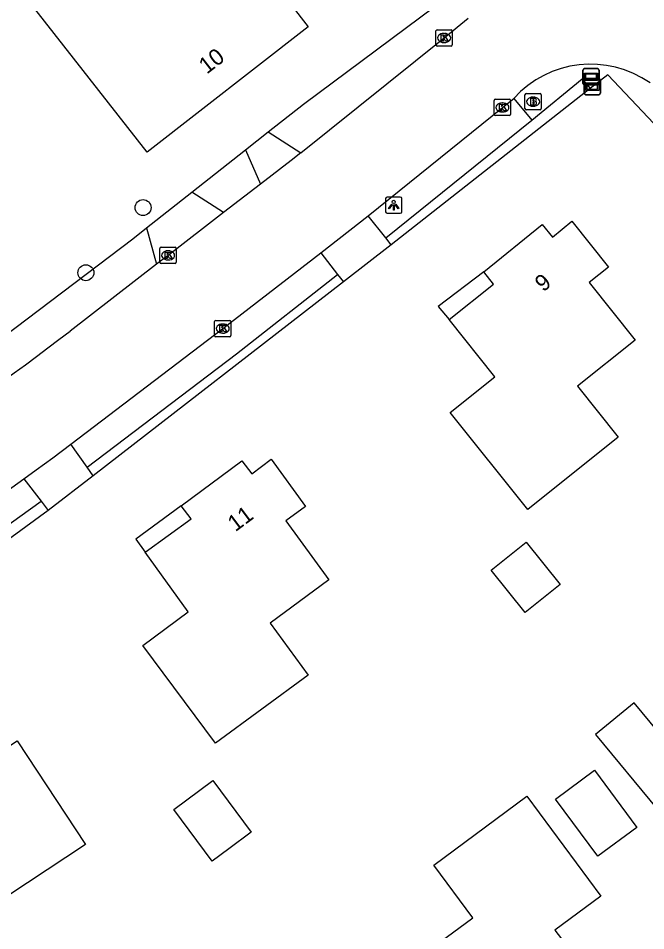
# Model space of a CAD drawing. Extents: x 162675 to 163482, y 379761 to 381227.
# Drawn here: x 163292.2 to 163330.7, y 380792.3 to 380848.3 of the extents above; entities that cross this region are included whole.
import ezdxf

# ---------------------------------------------------------------- set-up
doc = ezdxf.new("R2010")
doc.units = 0
for name, color, linetype in [('IMGEO_Boom', 7, 'Continuous'), ('IMGEO_Brandkraan', 7, 'Continuous'), ('IMGEO_Groenvoorziening', 7, 'Continuous'), ('IMGEO_Haag', 7, 'Continuous'), ('IMGEO_Kolk', 7, 'Continuous'), ('IMGEO_Lichtpunt', 7, 'Continuous'), ('IMGEO_Pand', 7, 'Continuous'), ('IMGEO_Pand_nummerreeks', 7, 'Continuous'), ('IMGEO_Pand_overbouw', 7, 'Continuous'), ('IMGEO_Parkeervlak_halfverhard', 7, 'Continuous'), ('IMGEO_Rijbaan_lokaal_gesloten', 7, 'Continuous'), ('IMGEO_Straatnaambord', 7, 'Continuous'), ('IMGEO_Verklikker', 7, 'Continuous'), ('IMGEO_Voetpad_halfverhard', 7, 'Continuous'), ('IMGEO_Voetpad_open', 7, 'Continuous')]:
    doc.layers.add(name, color=color, linetype=linetype)

msp = doc.modelspace()

# ---------------------------------------------------------------- linework, layer by layer
at = {"layer": 'IMGEO_Boom'}
for centre in [(163299.893, 380836.661), (163296.387, 380832.674)]:
    msp.add_circle(centre, 0.489, dxfattribs=at)
at = {"layer": 'IMGEO_Brandkraan'}
for p, q in [((163323.383, 380843.654), (163324.235, 380843.654)), ((163323.308, 380842.728), (163323.308, 380843.58)), ((163323.796, 380843.434), (163323.821, 380843.434)), ((163324.309, 380843.58), (163324.309, 380842.728)), ((163324.235, 380842.654), (163323.383, 380842.654)), ((163323.819, 380842.874), (163323.794, 380842.874))]:
    msp.add_line(p, q, dxfattribs=at)
for points in [[(163323.383, 380843.654), (163324.235, 380843.654)], [(163323.308, 380842.728), (163323.308, 380843.58)], [(163323.656, 380843.354), (163323.656, 380842.954), (163323.869, 380842.954)], [(163323.887, 380843.354), (163323.656, 380843.354)], [(163323.835, 380843.273), (163323.781, 380843.273), (163323.781, 380843.197)], [(163323.781, 380843.197), (163323.834, 380843.197)], [(163323.843, 380843.121), (163323.781, 380843.121), (163323.781, 380843.04)], [(163324.309, 380843.58), (163324.309, 380842.728)], [(163324.235, 380842.654), (163323.383, 380842.654)], [(163323.781, 380843.04), (163323.843, 380843.04)]]:
    msp.add_lwpolyline(points, dxfattribs=at)
for centre, radius, start, end in [((163323.385, 380843.578), 0.0765, 91.552, 178.448), ((163323.385, 380843.578), 0.0765, 91.552, 178.448), ((163324.233, 380843.578), 0.0765, 1.552, 88.448), ((163324.233, 380843.578), 0.0765, 1.552, 88.448), ((163323.836, 380843.235), 0.0379, 267.8285, 90.9355), ((163323.844, 380843.08), 0.0404, 269.8759, 90.5077), ((163323.891, 380843.209), 0.145, 59.4692, 91.5367), ((163323.916, 380843.256), 0.0922, 285.5137, 58.1501), ((163323.921, 380843.064), 0.105, 301.3115, 78.989), ((163323.385, 380842.73), 0.0765, 181.552, 268.448), ((163323.385, 380842.73), 0.0765, 181.552, 268.448), ((163323.875, 380843.205), 0.251, 268.6676, 293.5347), ((163324.233, 380842.73), 0.0765, 271.552, 358.448), ((163324.233, 380842.73), 0.0765, 271.552, 358.448)]:
    msp.add_arc(centre, radius, start, end, dxfattribs=at)
for centre, major_axis, ratio, start_param, end_param in [((163323.795, 380843.154), (-0.387, 0.002), 0.722429, 4.712389, 7.853982), ((163323.82, 380843.154), (-0.39, 0.002), 0.717154, 1.570796, 4.712389)]:
    msp.add_ellipse(centre, major_axis=major_axis, ratio=ratio, start_param=start_param, end_param=end_param, dxfattribs=at)
at = {"layer": 'IMGEO_Groenvoorziening'}
for points in [[(163307.569, 380841.308), (163309.722, 380843.007), (163318.685, 380849.672)], [(163358.343, 380813.122), (163328.383, 380844.802), (163327.309, 380843.958)], [(163302.894, 380837.618), (163306.169, 380840.203)], [(163271.872, 380815.173), (163286.296, 380824.946), (163299.265, 380834.754), (163300.104, 380835.416)]]:
    msp.add_lwpolyline(points, dxfattribs=at)
at = {"layer": 'IMGEO_Haag'}
for points in [[(163323.72, 380842.014), (163326.824, 380844.551), (163327.309, 380843.958)], [(163327.309, 380843.958), (163315.112, 380834.375)], [(163312.188, 380832.112), (163296.843, 380820.233)], [(163294.076, 380818.108), (163289.632, 380814.871), (163286.499, 380812.86)]]:
    msp.add_lwpolyline(points, dxfattribs=at)
at = {"layer": 'IMGEO_Kolk'}
for p, q in [((163317.928, 380847.559), (163318.78, 380847.559)), ((163317.853, 380846.633), (163317.853, 380847.485)), ((163318.341, 380847.339), (163318.366, 380847.339)), ((163318.854, 380847.485), (163318.854, 380846.633)), ((163318.78, 380846.559), (163317.928, 380846.559)), ((163318.364, 380846.779), (163318.339, 380846.779)), ((163321.425, 380842.375), (163321.425, 380843.227)), ((163321.5, 380843.301), (163322.352, 380843.301)), ((163321.913, 380843.081), (163321.938, 380843.081)), ((163322.426, 380843.227), (163322.426, 380842.375)), ((163321.936, 380842.521), (163321.911, 380842.521)), ((163322.352, 380842.301), (163321.5, 380842.301)), ((163300.928, 380833.309), (163300.928, 380834.161)), ((163301.003, 380834.235), (163301.855, 380834.235)), ((163301.929, 380834.161), (163301.929, 380833.309)), ((163301.416, 380834.015), (163301.441, 380834.015)), ((163301.855, 380833.235), (163301.003, 380833.235)), ((163301.439, 380833.455), (163301.414, 380833.455)), ((163304.281, 380828.822), (163304.281, 380829.674)), ((163304.356, 380829.748), (163305.208, 380829.748)), ((163305.282, 380829.674), (163305.282, 380828.822)), ((163304.769, 380829.528), (163304.794, 380829.528)), ((163305.208, 380828.748), (163304.356, 380828.748)), ((163304.792, 380828.968), (163304.767, 380828.968))]:
    msp.add_line(p, q, dxfattribs=at)
for points in [[(163317.928, 380847.559), (163318.78, 380847.559)], [(163317.853, 380846.633), (163317.853, 380847.485)], [(163318.174, 380847.259), (163318.297, 380847.259), (163318.297, 380847.108), (163318.427, 380847.259), (163318.591, 380847.259), (163318.445, 380847.108), (163318.598, 380846.859), (163318.446, 380846.859), (163318.361, 380847.023), (163318.297, 380846.956), (163318.297, 380846.859), (163318.174, 380846.859), (163318.174, 380847.259)], [(163318.854, 380847.485), (163318.854, 380846.633)], [(163318.78, 380846.559), (163317.928, 380846.559)], [(163321.425, 380842.375), (163321.425, 380843.227)], [(163321.5, 380843.301), (163322.352, 380843.301)], [(163322.426, 380843.227), (163322.426, 380842.375)], [(163321.746, 380843.001), (163321.869, 380843.001), (163321.869, 380842.85), (163321.999, 380843.001), (163322.163, 380843.001), (163322.017, 380842.85), (163322.17, 380842.601), (163322.018, 380842.601), (163321.933, 380842.765), (163321.869, 380842.698), (163321.869, 380842.601), (163321.746, 380842.601), (163321.746, 380843.001)], [(163322.352, 380842.301), (163321.5, 380842.301)], [(163300.928, 380833.309), (163300.928, 380834.161)], [(163301.003, 380834.235), (163301.855, 380834.235)], [(163301.929, 380834.161), (163301.929, 380833.309)], [(163301.249, 380833.935), (163301.372, 380833.935), (163301.372, 380833.784), (163301.502, 380833.935), (163301.666, 380833.935), (163301.52, 380833.784), (163301.673, 380833.535), (163301.521, 380833.535), (163301.436, 380833.699), (163301.372, 380833.632), (163301.372, 380833.535), (163301.249, 380833.535), (163301.249, 380833.935)], [(163301.855, 380833.235), (163301.003, 380833.235)], [(163304.281, 380828.822), (163304.281, 380829.674)], [(163304.356, 380829.748), (163305.208, 380829.748)], [(163305.282, 380829.674), (163305.282, 380828.822)], [(163304.602, 380829.448), (163304.725, 380829.448), (163304.725, 380829.297), (163304.855, 380829.448), (163305.019, 380829.448), (163304.873, 380829.297), (163305.026, 380829.048), (163304.874, 380829.048), (163304.789, 380829.212), (163304.725, 380829.145), (163304.725, 380829.048), (163304.602, 380829.048), (163304.602, 380829.448)], [(163305.208, 380828.748), (163304.356, 380828.748)]]:
    msp.add_lwpolyline(points, dxfattribs=at)
for centre, start, end in [((163317.93, 380847.483), 91.552, 178.448), ((163317.93, 380847.483), 91.552, 178.448), ((163318.778, 380847.483), 1.552, 88.448), ((163318.778, 380847.483), 1.552, 88.448), ((163317.93, 380846.635), 181.552, 268.448), ((163317.93, 380846.635), 181.552, 268.448), ((163318.778, 380846.635), 271.552, 358.448), ((163318.778, 380846.635), 271.552, 358.448), ((163321.502, 380843.225), 91.552, 178.448), ((163321.502, 380843.225), 91.552, 178.448), ((163322.35, 380843.225), 1.552, 88.448), ((163322.35, 380843.225), 1.552, 88.448), ((163321.502, 380842.377), 181.552, 268.448), ((163321.502, 380842.377), 181.552, 268.448), ((163322.35, 380842.377), 271.552, 358.448), ((163322.35, 380842.377), 271.552, 358.448), ((163301.005, 380834.159), 91.552, 178.448), ((163301.005, 380834.159), 91.552, 178.448), ((163301.853, 380834.159), 1.552, 88.448), ((163301.853, 380834.159), 1.552, 88.448), ((163301.005, 380833.311), 181.552, 268.448), ((163301.005, 380833.311), 181.552, 268.448), ((163301.853, 380833.311), 271.552, 358.448), ((163301.853, 380833.311), 271.552, 358.448), ((163304.358, 380829.672), 91.552, 178.448), ((163304.358, 380829.672), 91.552, 178.448), ((163305.206, 380829.672), 1.552, 88.448), ((163305.206, 380829.672), 1.552, 88.448), ((163304.358, 380828.824), 181.552, 268.448), ((163304.358, 380828.824), 181.552, 268.448), ((163305.206, 380828.824), 271.552, 358.448), ((163305.206, 380828.824), 271.552, 358.448)]:
    msp.add_arc(centre, 0.0765, start, end, dxfattribs=at)
for centre, major_axis, ratio, start_param, end_param in [((163318.34, 380847.059), (-0.387, 0.002), 0.722429, 4.712389, 7.853982), ((163318.365, 380847.059), (-0.39, 0.002), 0.717154, 1.570796, 4.712389), ((163321.912, 380842.801), (-0.387, 0.002), 0.722429, 4.712389, 7.853982), ((163321.937, 380842.801), (-0.39, 0.002), 0.717154, 1.570796, 4.712389), ((163301.415, 380833.735), (-0.387, 0.002), 0.722429, 4.712389, 7.853982), ((163301.44, 380833.735), (-0.39, 0.002), 0.717154, 1.570796, 4.712389), ((163304.768, 380829.248), (-0.387, 0.002), 0.722429, 4.712389, 7.853982), ((163304.793, 380829.248), (-0.39, 0.002), 0.717154, 1.570796, 4.712389)]:
    msp.add_ellipse(centre, major_axis=major_axis, ratio=ratio, start_param=start_param, end_param=end_param, dxfattribs=at)
at = {"layer": 'IMGEO_Lichtpunt'}
for p, q in [((163314.762, 380837.214), (163314.762, 380836.407)), ((163314.762, 380837.214), (163314.762, 380836.407)), ((163315.664, 380837.309), (163314.856, 380837.309)), ((163315.664, 380837.309), (163314.856, 380837.309)), ((163315.758, 380836.407), (163315.758, 380837.214)), ((163315.758, 380836.407), (163315.758, 380837.214)), ((163314.856, 380836.313), (163315.664, 380836.313)), ((163314.856, 380836.313), (163315.664, 380836.313))]:
    msp.add_line(p, q, dxfattribs=at)
for points in [[(163315.136, 380836.878), (163315.175, 380836.85), (163314.987, 380836.588), (163314.949, 380836.615), (163315.136, 380836.878)], [(163315.238, 380836.83), (163315.285, 380836.83), (163315.285, 380836.508), (163315.238, 380836.508), (163315.238, 380836.83)], [(163315.348, 380836.85), (163315.386, 380836.877), (163315.573, 380836.615), (163315.534, 380836.587), (163315.348, 380836.85)]]:
    msp.add_lwpolyline(points, dxfattribs=at)
msp.add_circle((163315.261, 380837.012), 0.0994, dxfattribs=at)
for centre, start, end in [((163314.856, 380837.214), 90, 180), ((163314.856, 380837.214), 90, 180), ((163315.664, 380837.214), 0, 90), ((163315.664, 380837.214), 0, 90), ((163314.856, 380836.407), 180, 270), ((163314.856, 380836.407), 180, 270), ((163315.664, 380836.407), 270, 0), ((163315.664, 380836.407), 270, 360)]:
    msp.add_arc(centre, 0.0946, start, end, dxfattribs=at)
at = {"layer": 'IMGEO_Pand'}
for points in [[(163296.403, 380852.525), (163298.244, 380850.163), (163304.416, 380854.973), (163310.02, 380847.748), (163300.136, 380840.05), (163292.666, 380849.618), (163296.403, 380852.525)], [(163320.778, 380832.718), (163324.371, 380835.636), (163325.001, 380834.86), (163326.178, 380835.827), (163328.428, 380833.01), (163327.246, 380832.066), (163330.065, 380828.535), (163326.535, 380825.716), (163329.029, 380822.593), (163323.481, 380818.16), (163318.729, 380824.106), (163321.468, 380826.294), (163318.654, 380829.815), (163321.372, 380831.976), (163320.778, 380832.718)], [(163299.887, 380809.82), (163302.664, 380811.885), (163300.032, 380815.545), (163302.843, 380817.588), (163302.234, 380818.386), (163305.958, 380821.154), (163306.554, 380820.351), (163307.746, 380821.24), (163309.858, 380818.353), (163308.647, 380817.466), (163311.293, 380813.849), (163307.677, 380811.202), (163310.017, 380808.002), (163304.332, 380803.841), (163299.887, 380809.82)], [(163321.243, 380814.45), (163323.381, 380816.158), (163325.459, 380813.558), (163323.321, 380811.849), (163321.243, 380814.45)], [(163331.461, 380799.75), (163333.818, 380801.697), (163329.996, 380806.322), (163327.639, 380804.375), (163331.461, 380799.75)], [(163288.249, 380797.071), (163284.483, 380794.589), (163282.001, 380798.354), (163280.734, 380797.519), (163279.459, 380799.457), (163278.756, 380800.527), (163280.017, 380801.357), (163279.46, 380802.176), (163283.297, 380804.714), (163283.89, 380803.912), (163286.786, 380805.821), (163289.262, 380802.063), (163292.184, 380803.988), (163296.366, 380797.642), (163290.445, 380793.74), (163288.249, 380797.071)], [(163327.568, 380802.181), (163330.163, 380798.678), (163327.781, 380796.914), (163325.186, 380800.417), (163327.568, 380802.181)], [(163304.164, 380801.551), (163306.517, 380798.385), (163305.152, 380797.37), (163304.127, 380796.609), (163301.774, 380799.774), (163304.164, 380801.551)], [(163323.426, 380800.597), (163327.961, 380794.475), (163325.149, 380792.383), (163325.748, 380791.578), (163324.943, 380790.982), (163327.029, 380788.166), (163320.525, 380783.311), (163319.927, 380784.113), (163318.696, 380783.244), (163316.547, 380786.143), (163317.763, 380787.044), (163315.673, 380789.863), (163320.103, 380793.145), (163317.715, 380796.367), (163323.426, 380800.597)]]:
    msp.add_lwpolyline(points, dxfattribs=at)
at = {"layer": 'IMGEO_Pand_overbouw'}
for points in [[(163320.778, 380832.718), (163317.989, 380830.592), (163318.654, 380829.815), (163321.372, 380831.976)], [(163302.234, 380818.386), (163299.455, 380816.349), (163300.032, 380815.545), (163302.843, 380817.588)]]:
    msp.add_lwpolyline(points, close=True, dxfattribs=at)
at = {"layer": 'IMGEO_Parkeervlak_halfverhard'}
for points in [[(163322.625, 380843.354), (163323.72, 380842.014)], [(163314.783, 380834.81), (163323.72, 380842.014)], [(163296.473, 380820.749), (163305.615, 380827.694), (163311.822, 380832.567)], [(163286.202, 380813.348), (163293.648, 380818.666)]]:
    msp.add_lwpolyline(points, dxfattribs=at)
at = {"layer": 'IMGEO_Rijbaan_lokaal_gesloten'}
for points in [[(163309.574, 380840.027), (163318.354, 380847.059), (163319.817, 380848.266)], [(163313.701, 380836.164), (163321.926, 380842.801), (163322.625, 380843.354)], [(163309.574, 380840.027), (163308.966, 380839.54), (163307.092, 380838.096)], [(163307.092, 380838.096), (163304.834, 380836.357)], [(163304.834, 380836.357), (163301.429, 380833.735), (163300.721, 380833.188)], [(163310.785, 380833.886), (163313.701, 380836.164)], [(163295.462, 380822.16), (163304.782, 380829.248), (163310.785, 380833.886)], [(163300.721, 380833.188), (163295.418, 380829.09)], [(163292.588, 380820.05), (163293.338, 380820.591), (163294.365, 380821.326), (163295.462, 380822.16)], [(163285.156, 380814.764), (163289.024, 380817.48), (163292.588, 380820.05)]]:
    msp.add_lwpolyline(points, dxfattribs=at)
for centre, radius, start, end in [((163327.339, 380839.107), 6.345, 55.0065, 137.984), ((163083.936, 381108.339), 350.292, 302.65851, 307.13762)]:
    msp.add_arc(centre, radius, start, end, dxfattribs=at)
at = {"layer": 'IMGEO_Straatnaambord'}
for p, q in [((163326.86, 380844.277), (163326.86, 380845.077)), ((163326.86, 380845.077), (163326.86, 380844.277)), ((163326.96, 380845.177), (163327.75, 380845.177)), ((163327.75, 380845.177), (163326.96, 380845.177)), ((163327.85, 380845.077), (163327.85, 380844.277)), ((163327.85, 380844.277), (163327.85, 380845.077)), ((163327.75, 380844.177), (163326.96, 380844.177)), ((163326.96, 380844.177), (163327.75, 380844.177))]:
    msp.add_line(p, q, dxfattribs=at)
for points in [[(163326.961, 380844.909), (163327.749, 380844.909), (163327.749, 380844.445), (163326.961, 380844.445), (163326.961, 380844.909)], [(163327.026, 380844.844), (163327.026, 380844.51), (163327.684, 380844.51), (163327.684, 380844.844), (163327.026, 380844.844)]]:
    msp.add_lwpolyline(points, dxfattribs=at)
for centre, start, end in [((163326.96, 380845.077), 90, 180), ((163326.96, 380845.077), 90, 180), ((163327.75, 380845.077), 0, 90), ((163327.75, 380845.077), 360, 90), ((163326.96, 380844.277), 180, 270), ((163326.96, 380844.277), 180, 270), ((163327.75, 380844.277), 270, 0), ((163327.75, 380844.277), 270, 0)]:
    msp.add_arc(centre, 0.1, start, end, dxfattribs=at)
at = {"layer": 'IMGEO_Verklikker'}
for p, q in [((163326.94, 380843.68), (163326.94, 380844.48)), ((163326.94, 380844.48), (163326.94, 380843.68)), ((163327.04, 380844.58), (163327.83, 380844.58)), ((163327.83, 380844.58), (163327.04, 380844.58)), ((163327.93, 380844.48), (163327.93, 380843.68)), ((163327.93, 380843.68), (163327.93, 380844.48)), ((163327.83, 380843.58), (163327.04, 380843.58)), ((163327.04, 380843.58), (163327.83, 380843.58))]:
    msp.add_line(p, q, dxfattribs=at)
for points in [[(163327.041, 380844.312), (163327.829, 380844.312), (163327.829, 380843.848), (163327.041, 380843.848), (163327.041, 380844.312)], [(163327.106, 380844.247), (163327.106, 380843.913), (163327.764, 380843.913), (163327.764, 380844.247), (163327.106, 380844.247)]]:
    msp.add_lwpolyline(points, dxfattribs=at)
for centre, start, end in [((163327.04, 380844.48), 90, 180), ((163327.04, 380844.48), 90, 180), ((163327.83, 380844.48), 0, 90), ((163327.83, 380844.48), 360, 90), ((163327.04, 380843.68), 180, 270), ((163327.04, 380843.68), 180, 270), ((163327.83, 380843.68), 270, 0), ((163327.83, 380843.68), 270, 0)]:
    msp.add_arc(centre, 0.1, start, end, dxfattribs=at)
at = {"layer": 'IMGEO_Voetpad_halfverhard'}
for points in [[(163306.169, 380840.203), (163307.569, 380841.308)], [(163307.569, 380841.308), (163309.574, 380840.027)], [(163306.169, 380840.203), (163307.092, 380838.096)], [(163300.104, 380835.416), (163302.894, 380837.618)], [(163304.834, 380836.357), (163302.894, 380837.618)], [(163300.104, 380835.416), (163300.721, 380833.188)]]:
    msp.add_lwpolyline(points, dxfattribs=at)
at = {"layer": 'IMGEO_Voetpad_open'}
for points in [[(163314.783, 380834.81), (163313.701, 380836.164)], [(163315.112, 380834.375), (163314.783, 380834.81)], [(163315.112, 380834.375), (163312.188, 380832.112)], [(163310.785, 380833.886), (163311.822, 380832.567)], [(163311.822, 380832.567), (163312.188, 380832.112)], [(163296.473, 380820.749), (163295.462, 380822.16)], [(163296.843, 380820.233), (163296.473, 380820.749)], [(163296.843, 380820.233), (163294.076, 380818.108)], [(163292.588, 380820.05), (163293.648, 380818.666)], [(163293.648, 380818.666), (163294.076, 380818.108)]]:
    msp.add_lwpolyline(points, dxfattribs=at)

# ---------------------------------------------------------------- texts
at = {"layer": 'IMGEO_Pand_nummerreeks'}
for s, rotation, p in [('10', 37.7121, (163303.802, 380844.81)), ('9', 39.0857, (163324.428, 380831.457)), ('11', 36.6327, (163305.554, 380816.767))]:
    msp.add_text(s, height=1, rotation=rotation, dxfattribs=at).set_placement(p)

doc.saveas('drawing.dxf')
